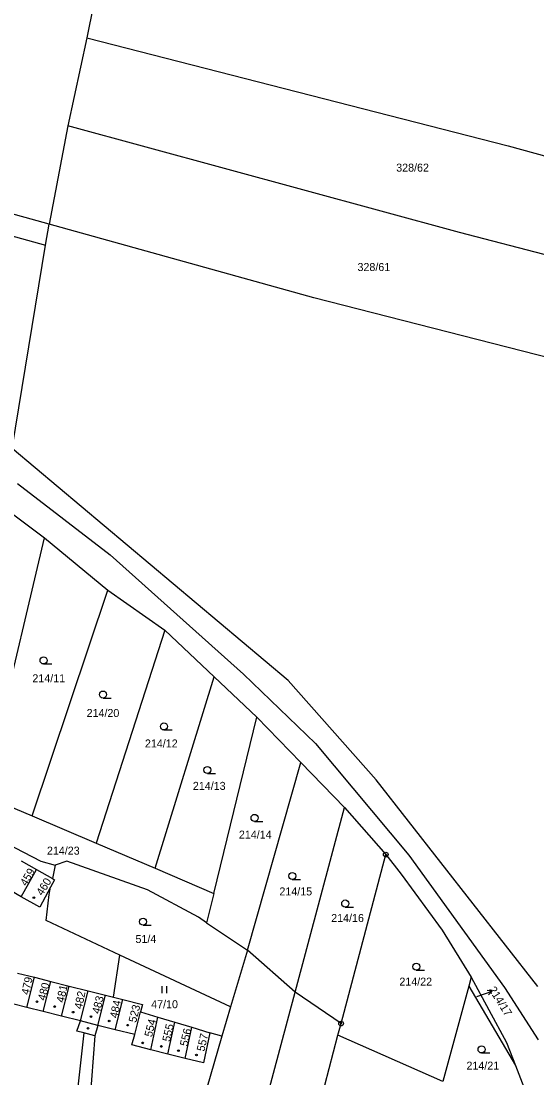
# Model space of a CAD drawing. Extents: x -783948 to -781889, y -1005870 to -1004430.
# Drawn here: x -782512.1 to -782402.5, y -1005350.5 to -1005126 of the extents above; entities that cross this region are included whole.
import ezdxf

# ---------------------------------------------------------------- set-up
doc = ezdxf.new("R2010")
doc.units = 0
for name, color, linetype in [('Vrstva 1', 7, 'Continuous'), ('Vrstva 2', 7, 'Continuous'), ('Vrstva 3', 7, 'Continuous'), ('Vrstva 4', 7, 'Continuous'), ('Vrstva 5', 7, 'Continuous'), ('Vrstva 6', 7, 'Continuous'), ('Vrstva 7', 7, 'Continuous'), ('Vrstva 8', 7, 'Continuous')]:
    doc.layers.add(name, color=color, linetype=linetype)

msp = doc.modelspace()

# ---------------------------------------------------------------- linework, layer by layer
at = {"layer": 'Vrstva 1'}
for p, q in [((-782498.13, -1005129.54), (-782502.18, -1005148.24)), ((-782502.18, -1005148.24), (-782506.17, -1005169.11)), ((-782506.17, -1005169.11), (-782533.94, -1005161.48)), ((-782535.05, -1005165.75), (-782506.92, -1005173.54)), ((-782506.92, -1005173.54), (-782506.17, -1005169.11)), ((-782514.05, -1005216.76), (-782506.92, -1005173.54)), ((-782514.79, -1005229.97), (-782507.16, -1005235.72)), ((-782520.1, -1005290.46), (-782507.16, -1005235.72)), ((-782507.16, -1005235.72), (-782493.66, -1005246.83)), ((-782509.75, -1005294.77), (-782493.66, -1005246.83)), ((-782493.66, -1005246.83), (-782481.57, -1005255.36)), ((-782481.57, -1005255.36), (-782496.14, -1005300.59)), ((-782481.57, -1005255.36), (-782471.12, -1005265.23)), ((-782483.62, -1005305.94), (-782471.12, -1005265.23)), ((-782471.12, -1005265.23), (-782462.04, -1005273.8)), ((-782471.19, -1005311.26), (-782462.04, -1005273.8)), ((-782462.04, -1005273.8), (-782452.64, -1005283.48)), ((-782464.02, -1005323.33), (-782452.64, -1005283.48)), ((-782452.64, -1005283.48), (-782443.41, -1005292.99)), ((-782520.1, -1005290.46), (-782509.75, -1005294.77)), ((-782509.75, -1005294.77), (-782496.14, -1005300.59)), ((-782453.91, -1005332.25), (-782443.41, -1005292.99)), ((-782443.41, -1005292.99), (-782434.63, -1005303.01)), ((-782496.14, -1005300.59), (-782483.62, -1005305.94)), ((-782444.13, -1005338.94), (-782434.63, -1005303.01)), ((-782512.15, -1005304.37), (-782508.83, -1005306.22)), ((-782504.89, -1005305.26), (-782505.48, -1005308.09)), ((-782483.62, -1005305.94), (-782471.19, -1005311.26)), ((-782512.1, -1005311.98), (-782508.83, -1005306.22)), ((-782508.83, -1005306.22), (-782505.48, -1005308.09)), ((-782512.1, -1005311.98), (-782515.41, -1005310.1)), ((-782505.88, -1005309.97), (-782508.16, -1005314.22)), ((-782508.16, -1005314.22), (-782512.1, -1005311.98)), ((-782471.19, -1005311.26), (-782472.71, -1005317.49)), ((-782472.71, -1005317.49), (-782464.02, -1005323.33)), ((-782464.02, -1005323.33), (-782467.63, -1005335.37)), ((-782453.91, -1005332.25), (-782464.02, -1005323.33)), ((-782492.49, -1005333.32), (-782491.14, -1005324.37)), ((-782467.63, -1005335.37), (-782491.14, -1005324.37)), ((-782512.9, -1005328.18), (-782509.31, -1005329.08)), ((-782510.93, -1005335.49), (-782509.31, -1005329.08)), ((-782509.31, -1005329.08), (-782505.8, -1005329.96)), ((-782507.43, -1005336.35), (-782505.8, -1005329.96)), ((-782505.8, -1005329.96), (-782501.91, -1005330.94)), ((-782416.46, -1005329.07), (-782416.99, -1005330.99)), ((-782503.53, -1005337.33), (-782501.91, -1005330.94)), ((-782501.91, -1005330.94), (-782497.87, -1005331.96)), ((-782499.48, -1005338.37), (-782497.87, -1005331.96)), ((-782497.87, -1005331.96), (-782494.19, -1005332.89)), ((-782495.8, -1005339.3), (-782494.19, -1005332.89)), ((-782494.19, -1005332.89), (-782492.49, -1005333.32)), ((-782467.9, -1005384.57), (-782453.91, -1005332.25)), ((-782444.13, -1005338.94), (-782453.91, -1005332.25)), ((-782416.99, -1005330.99), (-782422.52, -1005351.21)), ((-782416.99, -1005330.99), (-782407.07, -1005347.83)), ((-782510.93, -1005335.49), (-782513.7, -1005334.83)), ((-782492.49, -1005333.32), (-782490.51, -1005333.82)), ((-782492.12, -1005340.22), (-782490.51, -1005333.82)), ((-782507.43, -1005336.35), (-782510.93, -1005335.49)), ((-782503.53, -1005337.33), (-782507.43, -1005336.35)), ((-782499.48, -1005338.37), (-782503.53, -1005337.33)), ((-782487.95, -1005341.27), (-782486.73, -1005336.43)), ((-782486.73, -1005336.43), (-782483.1, -1005337.53)), ((-782467.63, -1005335.37), (-782469.45, -1005341.63)), ((-782495.8, -1005339.3), (-782496.47, -1005341.55)), ((-782492.12, -1005340.22), (-782495.8, -1005339.3)), ((-782484.55, -1005344.49), (-782483.1, -1005337.53)), ((-782483.1, -1005337.53), (-782479.46, -1005338.62)), ((-782480.93, -1005345.39), (-782479.46, -1005338.62)), ((-782479.46, -1005338.62), (-782475.83, -1005339.72)), ((-782444.78, -1005341.39), (-782444.13, -1005338.94)), ((-782498.81, -1005340.92), (-782501.89, -1005369.25)), ((-782496.47, -1005341.55), (-782498.93, -1005375.08)), ((-782496.47, -1005341.55), (-782498.81, -1005340.92)), ((-782487.95, -1005341.27), (-782492.12, -1005340.22)), ((-782469.45, -1005341.63), (-782480.52, -1005379.66)), ((-782477.27, -1005346.31), (-782475.83, -1005339.72)), ((-782475.83, -1005339.72), (-782472, -1005340.87)), ((-782469.45, -1005341.63), (-782472, -1005340.87)), ((-782457.2, -1005388.74), (-782444.78, -1005341.39)), ((-782422.52, -1005351.21), (-782444.78, -1005341.39)), ((-782480.93, -1005345.39), (-782484.55, -1005344.49)), ((-782477.27, -1005346.31), (-782480.93, -1005345.39)), ((-782407.07, -1005347.83), (-782402.72, -1005358.91))]:
    msp.add_line(p, q, dxfattribs=at)
for points in [[(-782483.01, -1005052.11), (-782490.87, -1005093.33), (-782498.13, -1005129.54)], [(-782498.13, -1005129.54), (-782408.58, -1005152.47), (-782355.25, -1005167.12), (-782360.07, -1005186.14)], [(-782360.07, -1005186.14), (-782418.96, -1005170.89), (-782502.18, -1005148.24)], [(-782360.07, -1005186.14), (-782367.58, -1005205.75), (-782449.91, -1005184.73), (-782506.17, -1005169.11)], [(-782402.29, -1005331.02), (-782436.69, -1005287.11), (-782455.38, -1005266.01), (-782514.05, -1005216.76)], [(-782519.05, -1005298.71), (-782507.97, -1005304.41), (-782504.89, -1005305.26)], [(-782434.63, -1005303.01), (-782431.37, -1005307.21), (-782422.6, -1005319.05), (-782416.46, -1005329.07)], [(-782472.71, -1005317.49), (-782474.43, -1005316.34), (-782485.29, -1005310.53), (-782502.44, -1005304.44), (-782504.89, -1005305.26)], [(-782505.48, -1005308.09), (-782505.01, -1005308.36), (-782505.88, -1005309.97)], [(-782491.14, -1005324.37), (-782506.82, -1005317.04), (-782506.2, -1005311.51), (-782505.88, -1005309.97)], [(-782416.46, -1005329.07), (-782408.99, -1005342.97), (-782407.07, -1005347.83)], [(-782490.51, -1005333.82), (-782486.34, -1005334.87), (-782486.73, -1005336.43)], [(-782498.81, -1005340.92), (-782500.28, -1005340.53), (-782499.48, -1005338.37)], [(-782484.55, -1005344.49), (-782488.62, -1005343.47), (-782487.95, -1005341.27)], [(-782472, -1005340.87), (-782473.39, -1005347.28), (-782477.27, -1005346.31)]]:
    msp.add_lwpolyline(points, dxfattribs=at)
at = {"layer": 'Vrstva 3'}
for p, q in [((-782507.36, -1005262.53), (-782505.61, -1005262.53)), ((-782494.72, -1005269.78), (-782492.97, -1005269.78)), ((-782481.77, -1005276.55), (-782480.02, -1005276.55)), ((-782472.53, -1005285.8), (-782470.78, -1005285.8)), ((-782462.51, -1005295.98), (-782460.76, -1005295.98)), ((-782454.49, -1005308.32), (-782452.74, -1005308.32)), ((-782443.24, -1005314.17), (-782441.49, -1005314.17)), ((-782486.21, -1005318.03), (-782484.46, -1005318.03)), ((-782428.14, -1005327.59), (-782426.39, -1005327.59)), ((-782482.18, -1005332.49), (-782482.18, -1005330.99)), ((-782481.18, -1005332.49), (-782481.18, -1005330.99)), ((-782414.26, -1005345.17), (-782412.51, -1005345.17))]:
    msp.add_line(p, q, dxfattribs=at)
for centre in [(-782507.36, -1005261.78), (-782494.72, -1005269.03), (-782481.77, -1005275.8), (-782472.53, -1005285.05), (-782462.51, -1005295.23), (-782454.49, -1005307.57), (-782443.24, -1005313.42), (-782486.21, -1005317.28), (-782428.14, -1005326.84), (-782414.26, -1005344.42)]:
    msp.add_circle(centre, 0.75, dxfattribs=at)
at = {"layer": 'Vrstva 4'}
msp.add_line((-782495.8, -1005339.3), (-782499.48, -1005338.37), dxfattribs=at)
at = {"layer": 'Vrstva 5'}
for centre in [(-782509.41, -1005312.16), (-782508.76, -1005334.28), (-782504.99, -1005335.31), (-782501.08, -1005336.5), (-782497.29, -1005337.43), (-782493.41, -1005338.38), (-782489.49, -1005339.26), (-782497.9, -1005339.92), (-782486.29, -1005343.02), (-782482.32, -1005343.78), (-782478.68, -1005344.66), (-782474.86, -1005345.58)]:
    msp.add_circle(centre, 0.175, dxfattribs=at)
at = {"layer": 'Vrstva 6'}
for p, q in [((-782512.93, -1005224.22), (-782493.17, -1005239.34)), ((-782493.17, -1005239.34), (-782464.83, -1005264.73)), ((-782464.83, -1005264.73), (-782449.55, -1005279.42)), ((-782449.55, -1005279.42), (-782429.73, -1005303.14)), ((-782429.73, -1005303.14), (-782409.41, -1005331.25)), ((-782409.41, -1005331.25), (-782402.26, -1005342.4))]:
    msp.add_line(p, q, dxfattribs=at)
at = {"layer": 'Vrstva 7'}
for p, q in [((-782414.83, -1005333.03), (-782411.99, -1005332.05)), ((-782411.99, -1005332.05), (-782413.1, -1005331.91)), ((-782411.99, -1005332.05), (-782412.78, -1005332.85)), ((-782415.27, -1005333.18), (-782414.83, -1005333.03))]:
    msp.add_line(p, q, dxfattribs=at)
at = {"layer": 'Vrstva 8'}
for centre, radius in [((-782434.63, -1005303.01), 0.5), ((-782434.63, -1005303.01), 0.0303), ((-782444.13, -1005338.94), 0.5), ((-782444.13, -1005338.94), 0.0303)]:
    msp.add_circle(centre, radius, dxfattribs=at)

# ---------------------------------------------------------------- texts
at = {"layer": 'Vrstva 2'}
for s, p in [('328/62', (-782432.4, -1005157.94)), ('328/61', (-782440.63, -1005179.06)), ('214/11', (-782509.73, -1005266.42)), ('214/20', (-782498.21, -1005273.8)), ('214/12', (-782485.81, -1005280.27)), ('214/13', (-782475.62, -1005289.28)), ('214/14', (-782465.84, -1005299.63)), ('214/23', (-782506.64, -1005303.04)), ('214/15', (-782457.23, -1005311.7)), ('214/16', (-782446.22, -1005317.35)), ('51/4', (-782487.82, -1005321.8)), ('214/22', (-782431.73, -1005330.86)), ('47/10', (-782484.48, -1005335.66)), ('214/21', (-782417.47, -1005348.71))]:
    msp.add_text(s, height=1.7, dxfattribs=at).set_placement(p)
for s, rotation, p in [('459', 60, (-782510.99, -1005309.85)), ('460', 58, (-782507.6, -1005311.89)), ('479', 77, (-782510.49, -1005332.93)), ('480', 75, (-782507, -1005334.16)), ('481', 78, (-782503.03, -1005334.59)), ('482', 78, (-782499.21, -1005335.94)), ('214/17', 302, (-782412.81, -1005331.68)), ('483', 76, (-782495.45, -1005336.96)), ('484', 78, (-782491.65, -1005337.88)), ('523', 76, (-782487.69, -1005338.83)), ('554', 76, (-782484.32, -1005341.89)), ('555', 77, (-782480.5, -1005342.89)), ('556', 77, (-782476.77, -1005343.86)), ('557', 77, (-782473.19, -1005344.95))]:
    msp.add_text(s, height=1.7, rotation=rotation, dxfattribs=at).set_placement(p)

doc.saveas('drawing.dxf')
